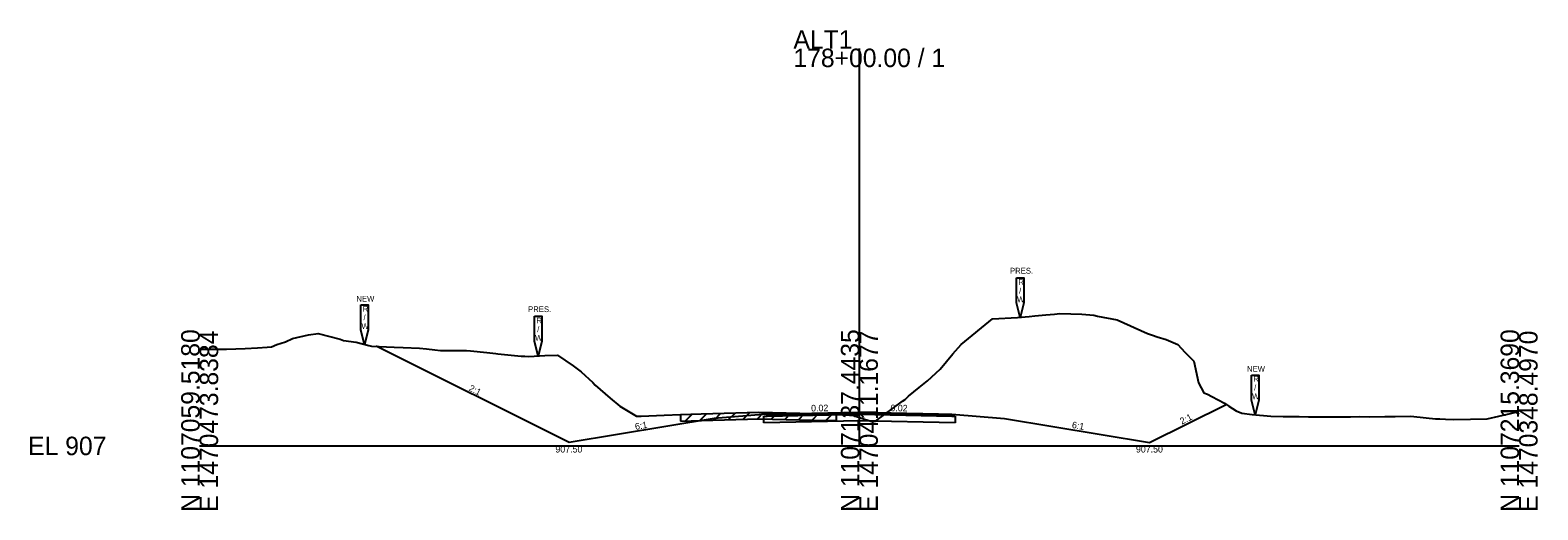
# Model space of a CAD drawing. Extents: x -26 to 2203, y -10 to 19568.
# Drawn here: x 1974.3 to 2202.8, y -9.7 to 63 of the extents above; entities that cross this region are included whole.
import ezdxf

# ---------------------------------------------------------------- set-up
doc = ezdxf.new("R2010")
doc.units = 0
for name, color, linetype in [('RD_GPK_XS_Cell', 7, 'Continuous'), ('RD_XS_Base', 7, 'Continuous'), ('RD_XS_ExGround', 7, 'Continuous'), ('RD_XS_ExPaveRet', 7, 'Continuous'), ('RD_XS_ExRW', 7, 'Continuous'), ('RD_XS_Greenside', 7, 'Continuous'), ('RD_XS_NewRW', 7, 'Continuous'), ('RD_XS_Pave', 7, 'Continuous'), ('RD_XS_TieSlope', 7, 'Continuous'), ('RD_XS_TX_Slope', 7, 'Continuous')]:
    doc.layers.add(name, color=color, linetype=linetype)

msp = doc.modelspace()

# ---------------------------------------------------------------- linework, layer by layer
at = {"layer": 'RD_GPK_XS_Cell'}
for p, q in [((2100, 0), (2100, 60.24)), ((2000, 0), (2100, 0)), ((2100, 0), (2200, 0))]:
    msp.add_line(p, q, dxfattribs=at)
at = {"layer": 'RD_XS_Base'}
for points in [[(2085.5, 4.51), (2086, 4.52), (2100, 4.8), (2114, 4.52), (2114.5, 4.51)], [(2085.5, 3.51), (2085.5, 4.51)], [(2114.5, 3.51), (2100, 3.8), (2085.5, 3.51)], [(2114.5, 4.51), (2114.5, 3.51)]]:
    msp.add_lwpolyline(points, dxfattribs=at)
at = {"layer": 'RD_XS_ExGround'}
msp.add_lwpolyline([(2000, 14.69), (2004.05, 14.69), (2006.92, 14.79), (2008.76, 14.87), (2010.24, 14.99), (2010.9, 15.04), (2011.71, 15.36), (2013.03, 15.77), (2014.09, 16.3), (2016.5, 16.85), (2017.94, 17.07), (2021.28, 16.21), (2021.79, 16), (2023.7, 15.71), (2025.64, 15.22), (2026.07, 15.15), (2029.49, 14.95), (2030.86, 14.94), (2033.34, 14.81), (2034.37, 14.7), (2035.64, 14.56), (2036.5, 14.48), (2037.19, 14.47), (2040.43, 14.47), (2041.04, 14.41), (2043.55, 14.16), (2044.89, 14.01), (2045.22, 13.98), (2048.74, 13.59), (2049.3, 13.59), (2049.88, 13.56), (2052.33, 13.72), (2054.26, 13.78), (2056.6, 12.16), (2057.84, 11.26), (2059.58, 9.61), (2059.97, 9.2), (2062.23, 7.24), (2063.67, 6.03), (2066.2, 4.5), (2066.94, 4.5), (2070.41, 4.64), (2072.87, 4.77), (2076.04, 4.87), (2084.77, 5.12), (2093.02, 4.92), (2096.46, 4.85), (2097.87, 4.71), (2099.11, 4.61), (2100, 4.31), (2100.34, 4.2), (2101.72, 3.76), (2102.46, 3.76), (2106.54, 6.78), (2106.92, 7.05), (2107.45, 7.53), (2109.05, 8.87), (2110.34, 9.88), (2112.23, 11.66), (2114.19, 13.97), (2115.45, 15.38), (2120.19, 19.28), (2123.99, 19.46), (2125.74, 19.63), (2126.6, 19.71), (2128.25, 19.88), (2129.59, 19.99), (2130.39, 20.08), (2133.7, 19.98), (2135.53, 19.82), (2136.11, 19.66), (2139.06, 19.14), (2143.65, 17.07), (2144.44, 16.81), (2145.15, 16.56), (2146.49, 16.13), (2148.26, 15.4), (2149.32, 14.24), (2150.72, 12.84), (2151.41, 9.55), (2152.19, 8.06), (2152.77, 7.84), (2153.4, 7.49), (2155.36, 6.47), (2156.02, 6.02), (2157.13, 5.31), (2157.98, 4.96), (2159.52, 4.78), (2162.39, 4.53), (2164.24, 4.46), (2164.89, 4.45), (2166.66, 4.45), (2168.09, 4.42), (2168.8, 4.42), (2169.68, 4.41), (2170.93, 4.43), (2171.94, 4.41), (2174.46, 4.42), (2175.79, 4.44), (2177.33, 4.42), (2179.64, 4.48), (2181.21, 4.48), (2183.49, 4.49), (2184.04, 4.45), (2187.34, 4.13), (2188, 4.09), (2188.83, 4.06), (2190.13, 4.03), (2192.61, 4.05), (2195.17, 4.12), (2198.7, 4.94), (2199.51, 5.13), (2200, 4.86)], dxfattribs=at)
at = {"layer": 'RD_XS_ExPaveRet'}
for p, q in [((2072.87, 4.77), (2072.87, 3.77)), ((2073.62, 3.79), (2074.65, 4.82)), ((2075.81, 3.86), (2076.84, 4.89)), ((2077.99, 3.92), (2079.02, 4.95)), ((2080.18, 3.99), (2081.21, 5.02)), ((2082.36, 4.05), (2083.39, 5.08)), ((2084.54, 4.11), (2085.53, 5.1)), ((2086.63, 4.07), (2087.6, 5.05)), ((2088.7, 4.02), (2089.67, 5)), ((2090.77, 3.97), (2091.75, 4.95)), ((2092.84, 3.92), (2093.82, 4.9)), ((2094.92, 3.88), (2095.9, 4.86)), ((2096.46, 4.85), (2096.46, 3.85))]:
    msp.add_line(p, q, dxfattribs=at)
msp.add_lwpolyline([(2072.87, 3.77), (2076.07, 3.87), (2084.78, 4.12), (2092.99, 3.92), (2096.46, 3.85)], dxfattribs=at)
at = {"layer": 'RD_XS_ExRW'}
for points in [[(2123.83, 25.51), (2124.93, 25.51), (2124.93, 21.68), (2124.38, 19.49), (2123.83, 21.68)], [(2050.78, 19.66), (2051.87, 19.66), (2051.87, 15.83), (2051.32, 13.65), (2050.78, 15.83)]]:
    msp.add_lwpolyline(points, close=True, dxfattribs=at)
at = {"layer": 'RD_XS_Greenside'}
for points in [[(2086, 4.83), (2078, 4.17)], [(2114, 4.83), (2122, 4.17)], [(2078, 4.17), (2056, 0.5)], [(2122, 4.17), (2144, 0.5)]]:
    msp.add_lwpolyline(points, dxfattribs=at)
at = {"layer": 'RD_XS_NewRW'}
for points in [[(2024.45, 21.4), (2025.55, 21.4), (2025.55, 17.57), (2025, 15.38), (2024.45, 17.57)], [(2159.45, 10.75), (2160.55, 10.75), (2160.55, 6.93), (2160, 4.74), (2159.45, 6.93)]]:
    msp.add_lwpolyline(points, close=True, dxfattribs=at)
at = {"layer": 'RD_XS_Pave'}
for points in [[(2086, 4.83), (2088, 4.87), (2100, 5.11), (2112, 4.87), (2114, 4.83)], [(2086, 4.67), (2100, 4.95), (2114, 4.67)], [(2114, 4.67), (2100, 4.95), (2086, 4.67)], [(2086, 4.67), (2086, 4.83)], [(2114, 4.52), (2100, 4.8), (2086, 4.52)], [(2086, 4.52), (2086, 4.67)], [(2114, 4.83), (2114, 4.67)], [(2114, 4.67), (2114, 4.52)]]:
    msp.add_lwpolyline(points, dxfattribs=at)
at = {"layer": 'RD_XS_TieSlope'}
for points in [[(2056, 0.5), (2026.78, 15.11)], [(2144, 0.5), (2155.61, 6.3)]]:
    msp.add_lwpolyline(points, dxfattribs=at)

# ---------------------------------------------------------------- texts
at = {"layer": 'RD_GPK_XS_Cell'}
for s, p in [('ALT1', (2090, 60.24)), ('178+00.00 / 1', (2090, 57.44)), ('EL 907', (1974, -1.4))]:
    msp.add_text(s, height=2.8, dxfattribs=at).set_placement(p)
for s, p in [('N 1107059.5180', (2000, -10)), ('E 1470473.8384', (2002.8, -10)), ('N 1107137.4435', (2100, -10)), ('E 1470411.1677', (2102.8, -10)), ('N 1107215.3690', (2200, -10)), ('E 1470348.4970', (2202.8, -10))]:
    msp.add_text(s, height=2.8, rotation=90, dxfattribs=at).set_placement(p)
at = {"layer": 'RD_XS_ExRW'}
for s, p in [('PRES.', (2122.83, 26.13)), ('R', (2124.09, 24.42)), ('/', (2124.21, 23.1)), ('PRES.', (2049.78, 20.29)), ('W', (2123.91, 21.79)), ('R', (2051.04, 18.57)), ('W', (2050.85, 15.95)), ('/', (2051.16, 17.26))]:
    msp.add_text(s, height=0.875, dxfattribs=at).set_placement(p)
at = {"layer": 'RD_XS_NewRW'}
for s, p in [('NEW', (2023.75, 21.88)), ('R', (2024.71, 20.36)), ('W', (2024.53, 17.73)), ('/', (2024.83, 19.05)), ('NEW', (2158.75, 11.24)), ('R', (2159.71, 9.72)), ('/', (2159.83, 8.4)), ('W', (2159.53, 7.09))]:
    msp.add_text(s, height=0.875, dxfattribs=at).set_placement(p)
at = {"layer": 'RD_XS_TX_Slope'}
for s, rotation, p in [('2:1', 333.4349, (2040.7, 8.43)), ('0.02', 1.1458, (2092.69, 5.22)), ('0.02', 358.8542, (2104.7, 5.27)), ('2:1', 26.5651, (2148.89, 3.22)), ('6:1', 9.4642, (2066.07, 2.43)), ('6:1', 350.5358, (2132.16, 2.73))]:
    msp.add_text(s, height=1, rotation=rotation, dxfattribs=at).set_placement(p)
for p in [(2053.92, -1), (2141.92, -1)]:
    msp.add_text('907.50', height=1, dxfattribs=at).set_placement(p)

doc.saveas('drawing.dxf')
